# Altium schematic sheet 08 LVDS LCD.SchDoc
size 420 x 297 mm; DocumentNumber: 8; SheetNumber: 8; SheetTotal: 12
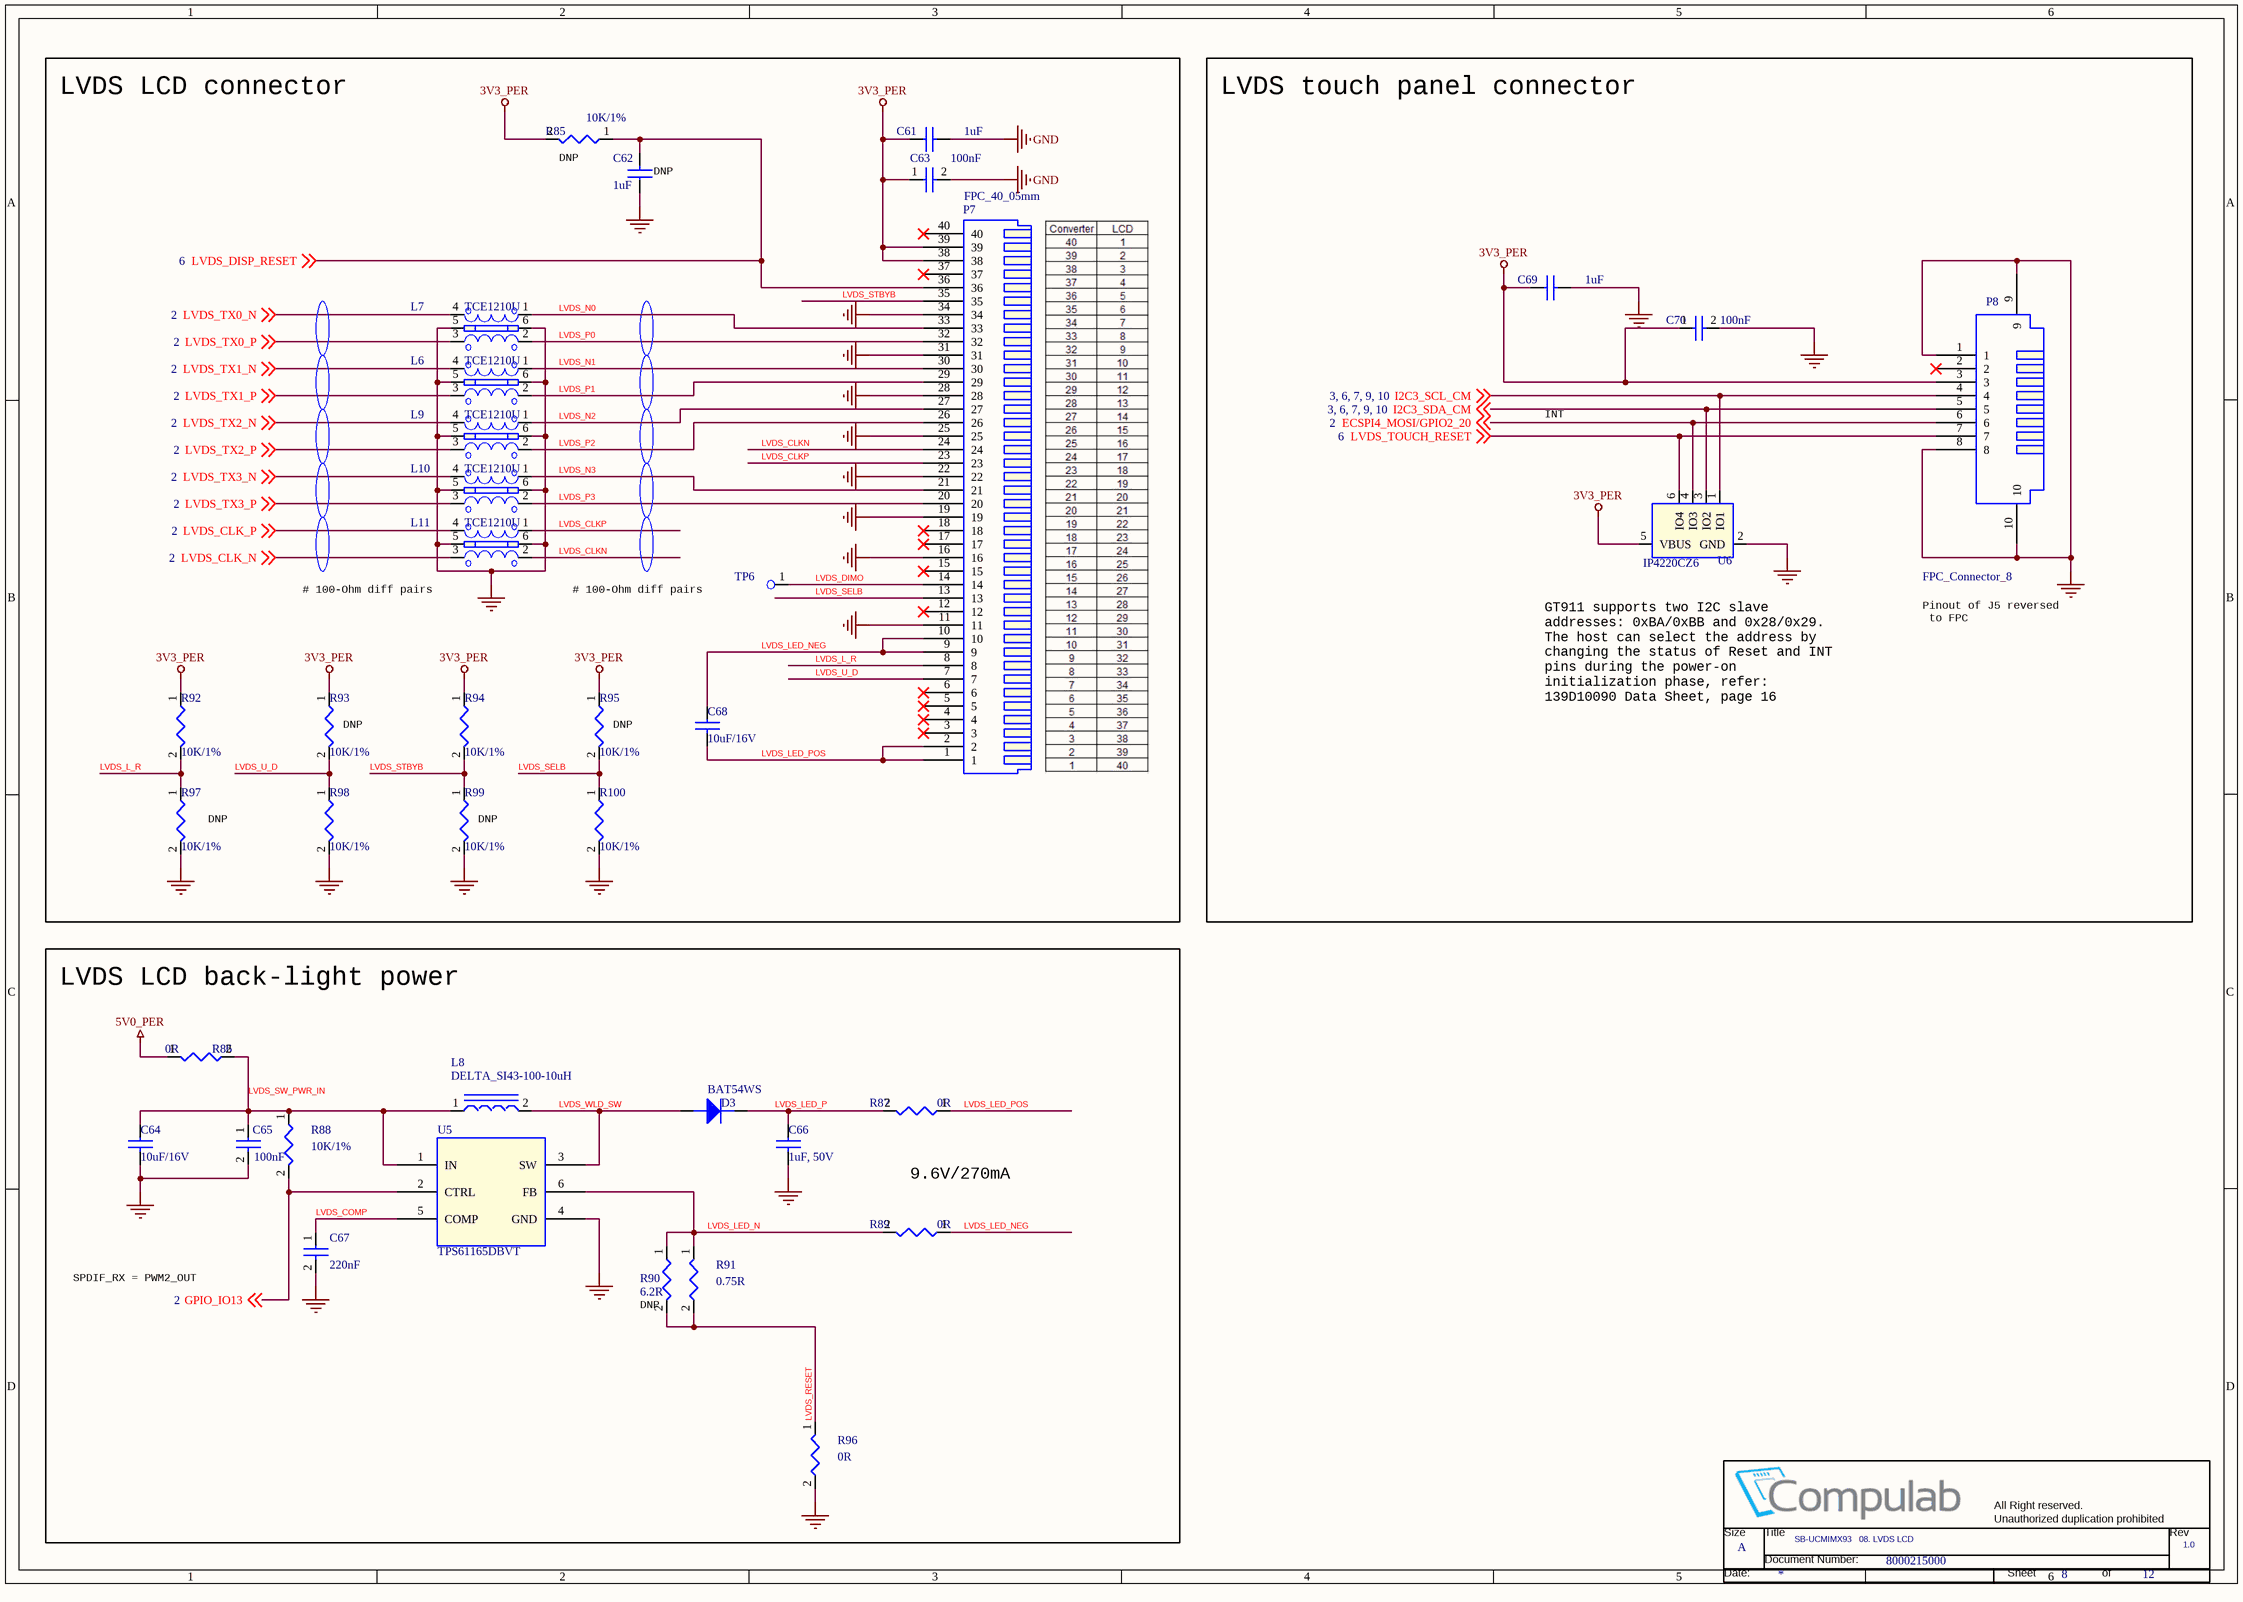
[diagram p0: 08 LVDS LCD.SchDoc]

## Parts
*  Title: SB-UCMIMX93   08. LVDS LCD  Doc: 8000215000  RevCode: 1.0  Page Size: A  Page Number: 8  Page Count: 12  (hidden comment: CompuLabTitleBlk)  (graphical)
C61  1uF  [RC0402]
C62  1uF  [RC0402]
C63  100nF  [RC0402]
C64  10uF/16V  [RC0603]
C65  100nF  [RC0402]
C66  1uF, 50V  [RC0603]
C67  220nF  [RC0402]
C68  10uF/16V  [RC0603]
C69  1uF  [RC0402]
C70  100nF  [RC0402]
D3  BAT54WS  [SOD-323]
L6  TCE1210U  [EMI1012-ESD]
L7  TCE1210U  [EMI1012-ESD]
L8  DELTA_SI43-100-10uH  [IND4x4x2_5]
L9  TCE1210U  [EMI1012-ESD]
L10  TCE1210U  [EMI1012-ESD]
L11  TCE1210U  [EMI1012-ESD]
P7  FPC_40_05mm  [FPC05SM40-1]
P8  FPC_Connector_8  [FPC_8]
R85  10K/1%  [RC0402]
R86  0R  [RC1206]
R87  0R  [RC1206]
R88  10K/1%  [RC0402]
R89  0R  [RC1206]
R90  6.2R  [RC0402]
R91  0.75R  [RC0402]
R92  10K/1%  [RC0402]
R93  10K/1%  [RC0402]
R94  10K/1%  [RC0402]
R95  10K/1%  [RC0402]
R96  0R  [RC0402]
R97  10K/1%  [RC0402]
R98  10K/1%  [RC0402]
R99  10K/1%  [RC0402]
R100  10K/1%  [RC0402]
TP6  TESTPOINT  [TESTPOINT]  (value not drawn)
U5  TPS61165DBVT  [SOT23-6]
U6  IP4220CZ6  [SOT23-6L]

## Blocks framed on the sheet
LVDS LCD connector: C61-C63 C68 L6 L7 L9-L11 P7 R85 R92-R95 R97-R100 TP6
LVDS touch panel connector: C69 C70 P8 U6
LVDS LCD back-light power: C64-C67 D3 L8 R86-R91 R96 U5

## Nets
3V3_PER: C61.1 C63.1 C69.1 C70.1 P7.38 P7.39 P8.3 R85.2 R92.1 R93.1 R94.1 R95.1 U6.5(VBUS)
5V0_PER: R86.1
GND: C61.2 C62.1 C63.2 C64.2 C65.2 C66.2 C67.2 C69.2 C70.2 L6.5(GND) L6.6(GND) L7.5(GND) L7.6(GND) L9.5(GND) L9.6(GND) L10.5(GND) L10.6(GND) L11.5(GND) L11.6(GND) P7.11 P7.16 P7.19 P7.22 P7.25 P7.28 P7.31 P7.34 P8.1 P8.8 P8.9 P8.10 R96.2 R97.2 R98.2 R99.2 R100.2 U5.4(GND) U6.2(GND)
ECSPI4_MOSI/GPIO2_20: P8.6 U6.4(IO3) ; off-sheet ECSPI4_MOSI/GPIO2_20
GPIO_IO13: R88.2 U5.2(CTRL) ; off-sheet GPIO_IO13
I2C3_SCL_CM: P8.4 U6.1(IO1) ; off-sheet I2C3_SCL_CM
I2C3_SDA_CM: P8.5 U6.3(IO2) ; off-sheet I2C3_SDA_CM
LVDS_CLK_N: L11.3 ; off-sheet LVDS_CLK_N
LVDS_CLK_P: L11.4 ; off-sheet LVDS_CLK_P
LVDS_CLKN: L11.2 P7.24
LVDS_CLKP: L11.1 P7.23
LVDS_COMP: C67.1 U5.5(COMP)
LVDS_DIMO: P7.14 TP6.1
LVDS_DISP_RESET: C62.2 P7.36 R85.1 ; off-sheet LVDS_DISP_RESET
LVDS_L_R: P7.8 R92.2 R97.1
LVDS_LED_N: R89.2 R90.1 R91.1 U5.6(FB)
LVDS_LED_NEG: C68.1 P7.9 P7.10 R89.1
LVDS_LED_P: C66.1 D3.CATHODE R87.2
LVDS_LED_POS: C68.2 P7.1 P7.2 R87.1
LVDS_N0: L7.1 P7.33
LVDS_N1: L6.1 P7.30
LVDS_N2: L9.1 P7.27
LVDS_N3: L10.1 P7.21
LVDS_P0: L7.2 P7.32
LVDS_P1: L6.2 P7.29
LVDS_P2: L9.2 P7.26
LVDS_P3: L10.2 P7.20
LVDS_RESET: R90.2 R91.2 R96.1
LVDS_SELB: P7.13 R95.2 R100.1
LVDS_STBYB: P7.35 R94.2 R99.1
LVDS_SW_PWR_IN: C64.1 C65.1 L8.1 R86.2 R88.1 U5.1(IN)
LVDS_TOUCH_RESET: P8.7 U6.6(IO4) ; off-sheet LVDS_TOUCH_RESET
LVDS_TX0_N: L7.4 ; off-sheet LVDS_TX0_N
LVDS_TX0_P: L7.3 ; off-sheet LVDS_TX0_P
LVDS_TX1_N: L6.4 ; off-sheet LVDS_TX1_N
LVDS_TX1_P: L6.3 ; off-sheet LVDS_TX1_P
LVDS_TX2_N: L9.4 ; off-sheet LVDS_TX2_N
LVDS_TX2_P: L9.3 ; off-sheet LVDS_TX2_P
LVDS_TX3_N: L10.4 ; off-sheet LVDS_TX3_N
LVDS_TX3_P: L10.3 ; off-sheet LVDS_TX3_P
LVDS_U_D: P7.7 R93.2 R98.1
LVDS_WLD_SW: D3.ANODE L8.2 U5.3(SW)

Not connected (* = marked no-connect by the designer): P7 3* 4* 5* 6* 12* 15* 17* 18* 37* 40*; P8 2*

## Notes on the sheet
- (near R85) DNP
- (near C62) DNP
- INT
- # 100-Ohm diff pairs
- Pinout of J5 reversed
  to FPC
- (near R93) DNP
- (near R95) DNP
- GT911 supports two I2C slave
  addresses: 0xBA/0xBB and 0x28/0x29.
  The host can select the address by
  changing the status of Reset and INT
  pins during the power-on
  initialization phase, refer:
  139D10090 Data Sheet, page 16
- (near R97) DNP
- (near R99) DNP
- 9.6V/270mA
- SPDIF_RX = PWM2_OUT
- (near R90) DNP

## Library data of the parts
C61 C69 = 1uF,X5R,6.3V,0402: P/N: 151B10500S
C62 = 1uF,X5R,6.3V,0402: P/N: 151B10500S; CLABCONF0: DNP
C63 C65 C70 = 100nF, 10V, X7R, 10%, 0402_Dup1: P/N: 151B10400S
C64 C68 = 10uF,6.3V,0603,20%X5R_Dup1: P/N: 151C10610S
C66 = 1uF,X5R,6.3V,0402: P/N: 151D10510S
C67 = 100nF, 10V, X7R, 10%, 0402: P/N: 151C22400S
D3 = BAT54WS_0: P/N: 130E05402S
L6 L7 L9-L11 = ESD_CHOKE_DIFFx2_10: P/N: 142D11801S
L8 = INC DELTA SI43-100, 10uH: P/N: 147A10001S; CLABCONF1: <null>
P7 = FPC_40_05mm: P/N: 182P04001S
P8 = FPC_Connector_6: P/N: 182P00803S
R85 = 10K,1%,0402,1/16W_0_Dup1: P/N: 161C10021S; CLABCONF0: DNP
R86 R87 R89 = 0R, 1206: P/N: 161F00005S
R88 = 10K,1%,0402,1/16W_0_Dup1: P/N: 161C10021S
R90 = 2.2R,5%,0402,1/16W: P/N: 161C06R25S; CLABCONF0: DNP
R91 = 2.2R,5%,0402,1/16W: P/N: 161C0R751S
R92 R94 R98 R100 = 10K,1%,0402,1/16W: P/N: 161C10021S
R93 R95 R97 R99 = 10K,1%,0402,1/16W: P/N: 161C10021S; CLABCONF0: DNP
R96 = 2.2R,5%,0402,1/16W: P/N: 161C00005S
TP6 = TESTPOINT: CLABCONF0: DNP
U5 = TPS61165DBVT: P/N: 123C15100S
U6 = IP4220CZ6_0: P/N: 132D42200S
